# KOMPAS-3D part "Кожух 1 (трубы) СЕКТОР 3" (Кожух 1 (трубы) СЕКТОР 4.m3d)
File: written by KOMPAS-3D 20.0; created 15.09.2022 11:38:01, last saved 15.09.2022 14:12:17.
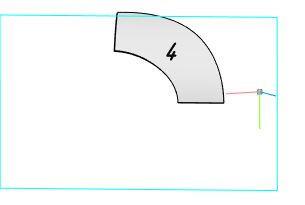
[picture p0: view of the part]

Document properties: Полное имя файла: D:\YAKOVLEV\ПРОЕКТЫ\ДЦ-2. ДП-7 Газопровод Окожушивание\ПРОБА Соединение труб. Окожушивание\Кожух 1 (трубы) СЕКТОР 4.m3d

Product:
- Part/product: Кожух 1 (трубы) СЕКТОР 3
    Материал: Сталь 45  ГОСТ 1050-2013 (density 7810 kg/m3)
    Масса: 116.939

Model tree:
1. Эскиз:1  (with: Обечайка:1)  (labels: Кожух 1 (трубы))
2. Обечайка:1  (labels: Кожух 1 (трубы))
     Расстояние 1 = -2450; Смещение 1 = -50; Толщина листового тела = 20
3. Сгиб(1) - Обечайка:1
     Радиус сгиба = 980; Коэффициент = 0.4; Величина сгиба = 10; Зазор = 1
4. Касательная плоскость:1  (with: Обечайка:1)
5. Эскиз:2  (with: Обечайка:1)  (labels: Кожух 1 (трубы))
6. Вырез в листовом теле:2
     Глубина выреза = 2400
7. Разогнуть:1  (with: Обечайка:1)
8. Эскиз:3  (with: Обечайка:1, Вырез в листовом теле:2)
9. Вырез в листовом теле:3
     Глубина выреза = 1000
10. Эскиз:4  (with: Обечайка:1, Вырез в листовом теле:2, Вырез в листовом теле:3)
11. Вырез в листовом теле:4
     Глубина выреза = 1000
12. Эскиз:5  (with: Обечайка:1, Вырез в листовом теле:3, Вырез в листовом теле:4)
13. Вырез в листовом теле:5
     Глубина выреза = 10
14. Фаска:1  (with: Вырез в листовом теле:2, Вырез в листовом теле:3, Вырез в листовом теле:4)
     Угол = 45; Длина 1 = 3; Длина 2 = 3
15. Эскиз:6  (with: Вырез в листовом теле:5)
16. Вырез в листовом теле:6
     Глубина выреза = 1000
17. Эскиз:7  (with: Обечайка:1)
18. Вырез в листовом теле:7
     Глубина выреза = 0.1
19. Фаска:2  (with: Вырез в листовом теле:6)
     Угол = 20; Длина 1 = 18; Длина 2 = 6.55146
20. Согнуть:1  (with: Обечайка:1)
21. Развертка  (labels: Сталь 45  ГОСТ 1050-2013)

Expressions: v140*2
Referenced files in D:\YAKOVLEV\ПРОЕКТЫ\ДЦ-2. ДП-7 Газопровод Окожушивание\ПРОБА Соединение труб. Окожушивание\: Соединение труб. Окожушивание -2.a3d
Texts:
  Соединение труб. Окожушивание\Труба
